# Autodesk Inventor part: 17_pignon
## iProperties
Shininess: 69.0
Length Units: 11269
Angle Units: 11279
Time Units: 11290
Mass Units: 11283
Length Display Precision: 3
Angle Display Precision: 2
Compacted: True
Created: 2002-11
Part Number: 17_pignon
Material: ABS (plastique)
Document SubType Name: Modélisation
Designer: FIEVET
Density: 1.06
Volumn: 0.33181193611860205
Area: 4.967957378605735
PropertySet Name: Model Information
Control State: 0
Master: False
Checked Out: False
Author: FIEVET
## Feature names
1. Extrusion1
2. Extrusion2
3. Réseau circulaire1 [Circular Pattern]
4. Extrusion4
